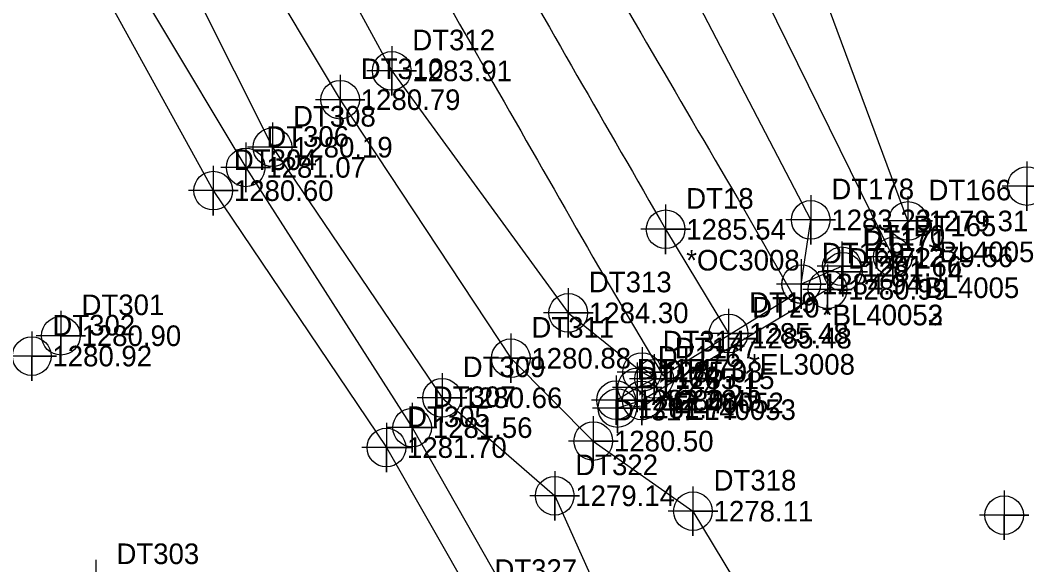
# Model space of a CAD drawing. Extents: x 1394009 to 1394411, y 957864 to 958364.
# Drawn here: x 1394095.7 to 1394217.7, y 958114.8 to 958180.8 of the extents above; entities that cross this region are included whole.
import ezdxf

# ---------------------------------------------------------------- set-up
doc = ezdxf.new("R2010")
doc.units = 0
for name, color, linetype in [('Exist DTM Breakline', 7, 'Continuous'), ('Exist DTM Breakline Cogo Comment', 7, 'Continuous'), ('Exist DTM Breakline Cogo Elevation', 7, 'Continuous'), ('Exist DTM Breakline Cogo Number', 7, 'Continuous'), ('Exist DTM Breakline Cogo Point CELL', 7, 'Continuous'), ('Exist DTM Crownline', 7, 'Continuous'), ('Exist DTM Regular Point Cogo Elevation', 7, 'Continuous'), ('Exist Roads EOP', 7, 'Continuous'), ('Exist Structure Minor Culvert Topo', 7, 'Continuous'), ('Exist Structure Minor Culvert Topo Terminator', 7, 'Continuous'), ('Exist Structure Minor Footbridge', 7, 'Continuous'), ('Exist Structure Minor Footbridge Terminator', 7, 'Continuous'), ('PH Exist DTM NCFMP LIDAR Elevation Point', 7, 'Continuous'), ('Raster_Level_0', 7, 'Continuous')]:
    doc.layers.add(name, color=color, linetype=linetype)

msp = doc.modelspace()

# ---------------------------------------------------------------- linework, layer by layer
at = {"layer": 'Exist DTM Breakline'}
for points in [[(1394201.5002, 958152.1258), (1394182.2949, 958191.1856), (1394144.2973, 958260.2559), (1394124.9997, 958296.4083), (1394109.3726, 958331.5215)], [(1394190.4005, 958148.8159), (1394191.5413, 958156.6052), (1394176.0985, 958186.3137), (1394153.7403, 958228.0077), (1394140.0661, 958255.9875), (1394118.8047, 958291.5046), (1394102.5433, 958327.8357)], [(1394203.3254, 958156.4773), (1394188.2939, 958197.0575), (1394161.6676, 958234.367), (1394146.9232, 958264.2671), (1394130.3208, 958303.8046)], [(1394070.2199, 958268.841), (1394083.0781, 958275.1225), (1394099.617, 958249.0394), (1394120.0982, 958212.652), (1394140.7402, 958174.6816), (1394162.1474, 958145.323), (1394171.088, 958138.1508)], [(1394070.1313, 958268.4251), (1394080.9574, 958242.6289), (1394101.6472, 958198.7507), (1394123.0372, 958162.9752), (1394143.223, 958131.4044), (1394156.1703, 958108.6674), (1394147.5951, 958089.3097), (1394152.395, 958060.7909)], [(1394078.4681, 958267.2162), (1394077.4426, 958263.4985), (1394090.7676, 958239.7722), (1394107.7408, 958202.4417), (1394126.2755, 958165.4231), (1394146.8464, 958135.0295)], [(1394078.4815, 958267.2528), (1394082.9126, 958267.3867), (1394095.8187, 958243.0525), (1394113.4272, 958206.3553), (1394134.4907, 958171.1858), (1394155.1759, 958139.8204), (1394165.1856, 958129.7757), (1394177.2665, 958121.2673), (1394190.9858, 958098.52), (1394181.5225, 958090.4285), (1394174.2125, 958080.1878)], [(1394065.3665, 958259.7005), (1394076.2432, 958241.6096), (1394098.862, 958196.9887), (1394119.1062, 958160.1529), (1394140.102, 958128.983), (1394150.6899, 958110.4316), (1394136.5853, 958093.0812), (1394143.0953, 958059.9522)], [(1394190.4413, 958148.8477), (1394195.3121, 958150.9751), (1394195.4345, 958150.3212), (1394193.5814, 958148.1809), (1394171.0515, 958134.7072), (1394168.1006, 958133.782), (1394167.9498, 958134.7422), (1394170.5014, 958136.2905), (1394172.56, 958137.3308)], [(1394171.088, 958138.1508), (1394172.56, 958137.3308)], [(1394146.8464, 958135.0295), (1394160.4995, 958123.1391), (1394167.05, 958108.5477), (1394161.6029, 958087.1443)]]:
    msp.add_lwpolyline(points, dxfattribs=at)
at = {"layer": 'Exist DTM Breakline Cogo Point CELL'}
for points in [[(1394140.7402, 958177.6816), (1394140.7402, 958171.6816), (1394140.7402, 958174.6816), (1394143.7402, 958174.6816), (1394137.7402, 958174.6816)], [(1394134.4907, 958174.1858), (1394134.4907, 958168.1858), (1394134.4907, 958171.1858), (1394137.4907, 958171.1858), (1394131.4907, 958171.1858)], [(1394126.2755, 958168.4231), (1394126.2755, 958162.4231), (1394126.2755, 958165.4231), (1394129.2755, 958165.4231), (1394123.2755, 958165.4231)], [(1394123.0372, 958165.9752), (1394123.0372, 958159.9752), (1394123.0372, 958162.9752), (1394126.0372, 958162.9752), (1394120.0372, 958162.9752)], [(1394119.1062, 958163.1529), (1394119.1062, 958157.1529), (1394119.1062, 958160.1529), (1394122.1062, 958160.1529), (1394116.1062, 958160.1529)], [(1394191.5413, 958159.6052), (1394191.5413, 958153.6052), (1394191.5413, 958156.6052), (1394194.5413, 958156.6052), (1394188.5413, 958156.6052)], [(1394203.3254, 958159.4773), (1394203.3254, 958153.4773), (1394203.3254, 958156.4773), (1394206.3254, 958156.4773), (1394200.3254, 958156.4773)], [(1394201.5002, 958155.1258), (1394201.5002, 958149.1258), (1394201.5002, 958152.1258), (1394204.5002, 958152.1258), (1394198.5002, 958152.1258)], [(1394195.3121, 958153.9751), (1394195.3121, 958147.9751), (1394195.3121, 958150.9751), (1394198.3121, 958150.9751), (1394192.3121, 958150.9751)], [(1394195.4345, 958153.3212), (1394195.4345, 958147.3212), (1394195.4345, 958150.3212), (1394198.4345, 958150.3212), (1394192.4345, 958150.3212)], [(1394190.3903, 958151.8254), (1394190.3903, 958145.8254), (1394190.3903, 958148.8254), (1394193.3903, 958148.8254), (1394187.3903, 958148.8254)], [(1394190.4005, 958151.8159), (1394190.4005, 958145.8159), (1394190.4005, 958148.8159), (1394193.4005, 958148.8159), (1394187.4005, 958148.8159)], [(1394193.5814, 958151.1809), (1394193.5814, 958145.1809), (1394193.5814, 958148.1809), (1394196.5814, 958148.1809), (1394190.5814, 958148.1809)], [(1394162.1474, 958148.323), (1394162.1474, 958142.323), (1394162.1474, 958145.323), (1394165.1474, 958145.323), (1394159.1474, 958145.323)], [(1394155.1759, 958142.8204), (1394155.1759, 958136.8204), (1394155.1759, 958139.8204), (1394158.1759, 958139.8204), (1394152.1759, 958139.8204)], [(1394171.088, 958141.1508), (1394171.088, 958135.1508), (1394171.088, 958138.1508), (1394174.088, 958138.1508), (1394168.088, 958138.1508)], [(1394172.56, 958140.3308), (1394172.56, 958134.3308), (1394172.56, 958137.3308), (1394175.56, 958137.3308), (1394169.56, 958137.3308)], [(1394170.5014, 958139.2905), (1394170.5014, 958133.2905), (1394170.5014, 958136.2905), (1394173.5014, 958136.2905), (1394167.5014, 958136.2905)], [(1394146.8464, 958138.0295), (1394146.8464, 958132.0295), (1394146.8464, 958135.0295), (1394149.8464, 958135.0295), (1394143.8464, 958135.0295)], [(1394167.9498, 958137.7422), (1394167.9498, 958131.7422), (1394167.9498, 958134.7422), (1394170.9498, 958134.7422), (1394164.9498, 958134.7422)], [(1394171.0515, 958137.7072), (1394171.0515, 958131.7072), (1394171.0515, 958134.7072), (1394174.0515, 958134.7072), (1394168.0515, 958134.7072)], [(1394168.1006, 958136.782), (1394168.1006, 958130.782), (1394168.1006, 958133.782), (1394171.1006, 958133.782), (1394165.1006, 958133.782)], [(1394143.223, 958134.4044), (1394143.223, 958128.4044), (1394143.223, 958131.4044), (1394146.223, 958131.4044), (1394140.223, 958131.4044)], [(1394165.1856, 958132.7757), (1394165.1856, 958126.7757), (1394165.1856, 958129.7757), (1394168.1856, 958129.7757), (1394162.1856, 958129.7757)], [(1394140.102, 958131.983), (1394140.102, 958125.983), (1394140.102, 958128.983), (1394143.102, 958128.983), (1394137.102, 958128.983)], [(1394160.4995, 958126.1391), (1394160.4995, 958120.1391), (1394160.4995, 958123.1391), (1394163.4995, 958123.1391), (1394157.4995, 958123.1391)], [(1394177.2665, 958124.2673), (1394177.2665, 958118.2673), (1394177.2665, 958121.2673), (1394180.2665, 958121.2673), (1394174.2665, 958121.2673)]]:
    msp.add_lwpolyline(points, dxfattribs=at)
for centre in [(1394140.7402, 958174.6816), (1394134.4907, 958171.1858), (1394126.2755, 958165.4231), (1394123.0372, 958162.9752), (1394119.1062, 958160.1529), (1394191.5413, 958156.6052), (1394203.3254, 958156.4773), (1394201.5002, 958152.1258), (1394195.3121, 958150.9751), (1394195.4345, 958150.3212), (1394190.3903, 958148.8254), (1394190.4005, 958148.8159), (1394193.5814, 958148.1809), (1394162.1474, 958145.323), (1394155.1759, 958139.8204), (1394171.088, 958138.1508), (1394170.5014, 958136.2905), (1394172.56, 958137.3308), (1394146.8464, 958135.0295), (1394167.9498, 958134.7422), (1394168.1006, 958133.782), (1394171.0515, 958134.7072), (1394143.223, 958131.4044), (1394140.102, 958128.983), (1394165.1856, 958129.7757), (1394160.4995, 958123.1391), (1394177.2665, 958121.2673)]:
    msp.add_circle(centre, 2.344, dxfattribs=at)
at = {"layer": 'Exist DTM Crownline'}
msp.add_line((1394173.9492, 958155.4634), (1394181.5787, 958142.8315), dxfattribs=at)
msp.add_spline([(1394087.9321, 958316.4176), (1394109.0623, 958273.1922), (1394131.7594, 958230.1822), (1394152.5248, 958192.8438), (1394173.9492, 958155.4634)], degree=3, dxfattribs=at)
at = {"layer": 'Exist Roads EOP'}
for p, q in [((1394182.7363, 958159.1242), (1394189.4014, 958147.4537)), ((1394165.818, 958150.9033), (1394173.6661, 958137.6896))]:
    msp.add_line(p, q, dxfattribs=at)
msp.add_lwpolyline([(1394189.4014, 958147.4537), (1394173.6661, 958137.6896)], dxfattribs=at)
for points in [[(1394096.2145, 958320.2223), (1394117.2204, 958277.6897), (1394140.0936, 958234.4745), (1394160.6957, 958197.1466), (1394182.7363, 958159.1242)], [(1394078.897, 958312.8974), (1394101.0229, 958268.6968), (1394123.3315, 958225.72), (1394144.2526, 958188.5895), (1394165.818, 958150.9033)]]:
    msp.add_spline(points, degree=3, dxfattribs=at)
at = {"layer": 'Exist Structure Minor Culvert Topo Terminator'}
for points in [[(1394173.9492, 958158.4634), (1394173.9492, 958152.4634), (1394173.9492, 958155.4634), (1394176.9492, 958155.4634), (1394170.9492, 958155.4634)], [(1394181.5787, 958145.8315), (1394181.5787, 958139.8315), (1394181.5787, 958142.8315), (1394184.5787, 958142.8315), (1394178.5787, 958142.8315)]]:
    msp.add_lwpolyline(points, dxfattribs=at)
for centre in [(1394173.9492, 958155.4634), (1394181.5787, 958142.8315)]:
    msp.add_circle(centre, 2.344, dxfattribs=at)
at = {"layer": 'PH Exist DTM NCFMP LIDAR Elevation Point'}
for points in [[(1394217.7585, 958163.7088), (1394217.7585, 958157.7088), (1394217.7585, 958160.7088), (1394220.7585, 958160.7088), (1394214.7585, 958160.7088)], [(1394100.6346, 958145.5544), (1394100.6346, 958139.5544), (1394100.6346, 958142.5544), (1394103.6346, 958142.5544), (1394097.6346, 958142.5544)], [(1394097.1059, 958143.0857), (1394097.1059, 958137.0857), (1394097.1059, 958140.0857), (1394100.1059, 958140.0857), (1394094.1059, 958140.0857)], [(1394214.9941, 958123.785), (1394214.9941, 958117.785), (1394214.9941, 958120.785), (1394217.9941, 958120.785), (1394211.9941, 958120.785)], [(1394104.8722, 958115.3508), (1394104.8722, 958109.3508), (1394104.8722, 958112.3508), (1394107.8722, 958112.3508), (1394101.8722, 958112.3508)]]:
    msp.add_lwpolyline(points, dxfattribs=at)
for centre in [(1394217.7585, 958160.7088), (1394100.6346, 958142.5544), (1394097.1059, 958140.0857), (1394214.9941, 958120.785)]:
    msp.add_circle(centre, 2.344, dxfattribs=at)

# ---------------------------------------------------------------- texts
at = {"layer": 'Exist DTM Breakline Cogo Comment'}
for s, p in [('*BL40051', (1394205.8254, 958151.4773)), ('*BL4005', (1394204.0002, 958147.1258)), ('*BL40053', (1394192.8903, 958143.8254)), ('*BL40052', (1394192.9005, 958143.8159)), ('*EL40052', (1394173.588, 958133.1508)), ('*EL40053', (1394175.06, 958132.3308))]:
    msp.add_text(s, height=2.5, dxfattribs=at).set_placement(p)
at = {"layer": 'Exist DTM Breakline Cogo Elevation'}
for s, p in [('1283.91', (1394143.2402, 958173.4316)), ('1280.79', (1394136.9907, 958169.9358)), ('1280.19', (1394128.7755, 958164.1731)), ('1281.07', (1394125.5372, 958161.7252)), ('1280.60', (1394121.6062, 958158.9029)), ('1283.23', (1394194.0413, 958155.3552)), ('1279.31', (1394205.8254, 958155.2273)), ('1279.56', (1394204.0002, 958150.8758)), ('1281.66', (1394197.8121, 958149.7251)), ('1281.14', (1394197.9345, 958149.0712)), ('1284.94', (1394192.8903, 958147.5754)), ('1284.94', (1394192.9005, 958147.5659)), ('1280.99', (1394196.0814, 958146.9309)), ('1284.30', (1394164.6474, 958144.073)), ('1280.88', (1394157.6759, 958138.5704)), ('1285.08', (1394173.588, 958136.9008)), ('1285.15', (1394175.06, 958136.0808)), ('1284.51', (1394173.0014, 958135.0405)), ('1280.66', (1394149.3464, 958133.7795)), ('1282.28', (1394170.4498, 958133.4922)), ('1281.71', (1394170.6006, 958132.532)), ('1280.49', (1394173.5515, 958133.4572)), ('1281.56', (1394145.723, 958130.1544)), ('1281.70', (1394142.602, 958127.733)), ('1280.50', (1394167.6856, 958128.5257)), ('1279.14', (1394162.9995, 958121.8891)), ('1278.11', (1394179.7665, 958120.0173))]:
    msp.add_text(s, height=2.5, dxfattribs=at).set_placement(p)
at = {"layer": 'Exist DTM Breakline Cogo Number'}
for s, p in [('DT312', (1394143.2402, 958177.1816)), ('DT310', (1394136.9907, 958173.6858)), ('DT308', (1394128.7755, 958167.9231)), ('DT306', (1394125.5372, 958165.4752)), ('DT304', (1394121.6062, 958162.6529)), ('DT178', (1394194.0413, 958159.1052)), ('DT166', (1394205.8254, 958158.9773)), ('DT165', (1394204.0002, 958154.6258)), ('DT170', (1394197.8121, 958153.4751)), ('DT171', (1394197.9345, 958152.8212)), ('DT169', (1394192.8903, 958151.3254)), ('DT168', (1394192.9005, 958151.3159)), ('DT172', (1394196.0814, 958150.6809)), ('DT313', (1394164.6474, 958147.823)), ('DT311', (1394157.6759, 958142.3204)), ('DT314', (1394173.588, 958140.6508)), ('DT177', (1394175.06, 958139.8308)), ('DT176', (1394173.0014, 958138.7905)), ('DT309', (1394149.3464, 958137.5295)), ('DT175', (1394170.4498, 958137.2422)), ('DT173', (1394173.5515, 958137.2072)), ('DT174', (1394170.6006, 958136.282)), ('DT307', (1394145.723, 958133.9044)), ('DT305', (1394142.602, 958131.483)), ('DT317', (1394167.6856, 958132.2757)), ('DT322', (1394162.9995, 958125.6391)), ('DT318', (1394179.7665, 958123.7673)), ('DT327', (1394153.1899, 958112.9316))]:
    msp.add_text(s, height=2.5, dxfattribs=at).set_placement(p)
at = {"layer": 'Exist DTM Regular Point Cogo Elevation'}
for s, p in [('1280.90', (1394103.1346, 958141.3044)), ('1285.48', (1394184.4349, 958141.0114)), ('1280.92', (1394099.6059, 958138.8357))]:
    msp.add_text(s, height=2.5, dxfattribs=at).set_placement(p)
at = {"layer": 'Exist Structure Minor Culvert Topo'}
for s, p in [('DT18', (1394176.4492, 958157.9634)), ('DT19', (1394184.0787, 958145.3315))]:
    msp.add_text(s, height=2.5, dxfattribs=at).set_placement(p)
at = {"layer": 'Exist Structure Minor Footbridge'}
for s, p in [('*OC3008', (1394176.4492, 958150.4634)), ('*EL3008', (1394184.0787, 958137.8315))]:
    msp.add_text(s, height=2.5, dxfattribs=at).set_placement(p)
at = {"layer": 'Exist Structure Minor Footbridge Terminator'}
for s, p in [('1285.54', (1394176.4492, 958154.2134)), ('1285.48', (1394184.0787, 958141.5815))]:
    msp.add_text(s, height=2.5, dxfattribs=at).set_placement(p)
at = {"layer": 'Raster_Level_0'}
for s, p in [('DT301', (1394103.1346, 958145.0544)), ('DT20', (1394184.4349, 958144.7614)), ('DT302', (1394099.6059, 958142.5857)), ('DT303', (1394107.3722, 958114.8508))]:
    msp.add_text(s, height=2.5, dxfattribs=at).set_placement(p)

doc.saveas('drawing.dxf')
